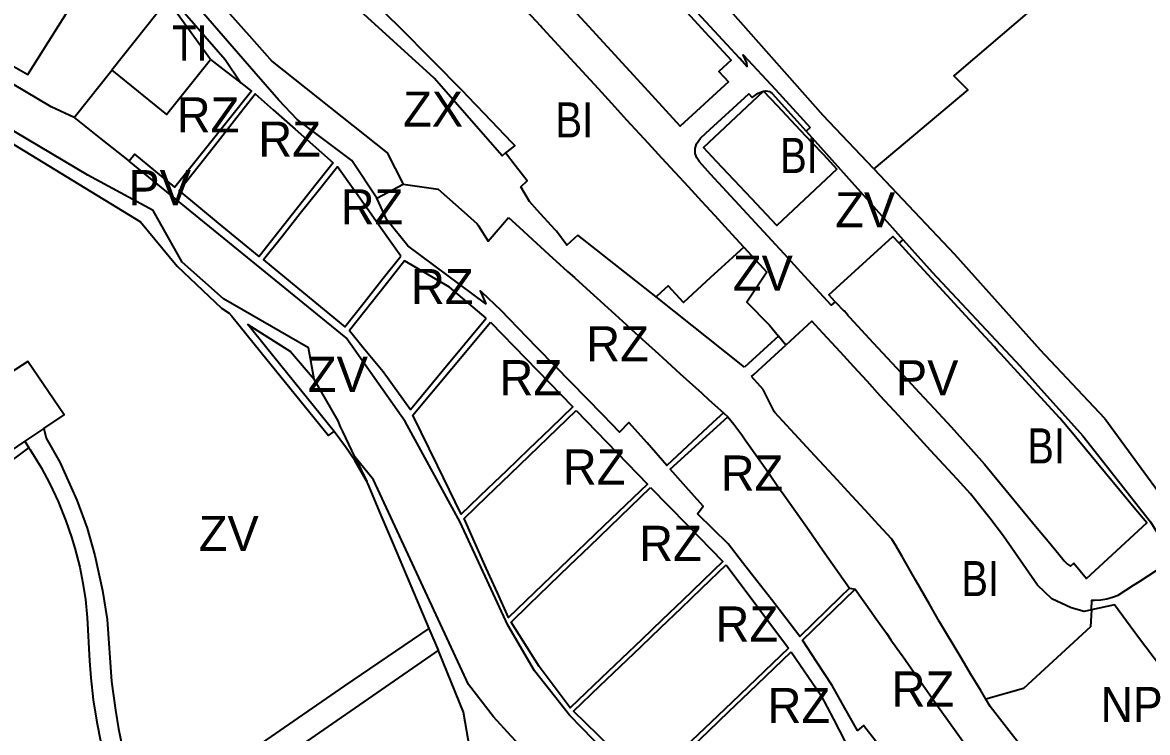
# Model space of a CAD drawing. Extents: x -650451 to -642268, y -1075216 to -1066610.
# Drawn here: x -646557.7 to -646077.2, y -1072296.6 to -1071993.3 of the extents above; entities that cross this region are included whole.
import ezdxf

# ---------------------------------------------------------------- set-up
doc = ezdxf.new("R2010")
doc.units = 0
doc.header["$LTSCALE"] = 6
doc.layers.add('1', color=7, linetype='Continuous', lineweight=35)
doc.layers.add('2', color=7, linetype='Continuous')
doc.layers.add('3', color=7, linetype='Continuous')

msp = doc.modelspace()

# ---------------------------------------------------------------- linework, layer by layer
at = {"layer": '1'}
for p, q in [((-646472.83, -1071985.44), (-646460.91, -1071998.89)), ((-646535.68, -1072033.89), (-646519.64, -1072013.69)), ((-646194.191, -1072055.797), (-646215.94, -1072032.8)), ((-646221.31, -1072038.09), (-646222.96, -1072039.72)), ((-646406.46, -1072068.39), (-646395.21, -1072062.3)), ((-646337.87, -1072073.42), (-646341.21, -1072069.74)), ((-646330.33, -1072081.74), (-646337.87, -1072073.42)), ((-646196.17, -1072069.75), (-646193.3, -1072072.98)), ((-646338.2, -1072087.54), (-646331.17, -1072093.93)), ((-646183.28, -1072087.62), (-646181.609, -1072086.079)), ((-646331.17, -1072093.93), (-646329.95, -1072095.03)), ((-646329.95, -1072095.03), (-646324.94, -1072099.59)), ((-646293.83, -1072105.24), (-646307.16, -1072094.67)), ((-646324.94, -1072099.59), (-646321.85, -1072102.39)), ((-646287.16, -1072110.52), (-646293.83, -1072105.24)), ((-646249.36, -1072140.5), (-646287.16, -1072110.52)), ((-646306.22, -1072116.58), (-646299.95, -1072122.27)), ((-646299.95, -1072122.27), (-646299.17, -1072122.98)), ((-646299.17, -1072122.98), (-646291.65, -1072129.81)), ((-646231.72, -1072131.08), (-646234.9, -1072127.22)), ((-646234.64, -1072133.77), (-646231.72, -1072131.08)), ((-646245.39, -1072143.64), (-646234.64, -1072133.77)), ((-646095.44, -1072162.47), (-646123.06, -1072133.18)), ((-646246.39, -1072144.56), (-646245.39, -1072143.64)), ((-646241.37, -1072150.02), (-646246.39, -1072144.56)), ((-646240.33, -1072152.1), (-646241.37, -1072150.02)), ((-646258.35, -1072160.04), (-646256.42, -1072161.7)), ((-646548.676, -1072166.737), (-646556.693, -1072172.159)), ((-646556.693, -1072172.159), (-646555.051, -1072174.933)), ((-646415.75, -1072178.82), (-646410.68, -1072189.36)), ((-646233.19, -1072194.16), (-646227.62, -1072202.1)), ((-646227.62, -1072202.1), (-646221.81, -1072210.37)), ((-646186.39, -1072214.03), (-646192.09, -1072207.86)), ((-646170.37, -1072241.84), (-646176.21, -1072231.64)), ((-646204.52, -1072235.01), (-646202.08, -1072235.38)), ((-646202.08, -1072235.38), (-646195.15, -1072245.18)), ((-646380.12, -1072261.44), (-646384.056, -1072252.138)), ((-646155.44, -1072267.16), (-646157.3, -1072264.05)), ((-646172.17, -1072277.7), (-646167.16, -1072284.79)), ((-646146.27, -1072282.34), (-646148.45, -1072278.73))]:
    msp.add_line(p, q, dxfattribs=at)
for points in [[(-646357.09, -1071925.59), (-646339.33, -1071906.58), (-646336.6, -1071910.5), (-646333.15, -1071915.44), (-646331.55, -1071917.74), (-646325.42, -1071925.87), (-646322.33, -1071930.79), (-646305.17, -1071949.86), (-646273.14, -1071985.13), (-646251.59, -1072008.34), (-646251.4, -1072008.54), (-646248.19, -1072012.02), (-646248.33, -1072010.57), (-646249.88, -1072007.03), (-646236.1, -1072021.93), (-646221.31, -1072038.09)], [(-646249.71, -1072089.21), (-646256.24, -1072082.11), (-646261.92, -1072075.92), (-646267.6, -1072069.74), (-646273.28, -1072063.55), (-646278.97, -1072057.37), (-646284.65, -1072051.18), (-646290.33, -1072045), (-646299.57, -1072034.94), (-646306.1, -1072027.84), (-646311.78, -1072021.65), (-646328.83, -1072003.1), (-646335.36, -1071995.99), (-646335.87, -1071995.44), (-646336.37, -1071994.89), (-646350.24, -1071979.79), (-646364.11, -1071964.7), (-646377.98, -1071949.6), (-646376.25, -1071948.01), (-646380.09, -1071943.87), (-646357.09, -1071925.59)], [(-646305.73, -1071933.35), (-646302.38, -1071937.06), (-646293.49, -1071946.89), (-646266.5, -1071975.69), (-646215.94, -1072032.8)], [(-646068.317, -1071937.555), (-646156.858, -1072013.393), (-646160, -1072016), (-646154, -1072022), (-646194.191, -1072055.797)], [(-646451.87, -1071956.88), (-646446.22, -1071959.67), (-646423.62, -1071970.84), (-646411.66, -1071980.54), (-646397.04, -1071994.94), (-646382.64, -1072009.55), (-646369.88, -1072022.49), (-646367.74, -1072024.72), (-646360.53, -1072032.22), (-646348.89, -1072044.34), (-646347.47, -1072045.83), (-646349.03, -1072047.09), (-646351.45, -1072049.03)], [(-646406.46, -1072068.39), (-646417.04, -1072052.27), (-646440.49, -1072034.75), (-646448.23, -1072026.42), (-646458.91, -1072014.27), (-646493.47, -1071974.228), (-646501.961, -1071969.983), (-646511.058, -1071967.447), (-646523.641, -1071965.612)], [(-646277.19, -1071985.4), (-646264.6, -1071999.11), (-646263.65, -1072000.13), (-646255.13, -1072009.41), (-646260.28, -1072014.15), (-646256.22, -1072018.57), (-646276.84, -1072037.51), (-646290.37, -1072022.79), (-646317.43, -1071993.33), (-646342.81, -1071965.72)], [(-646565.01, -1072016.41), (-646561.43, -1072012.01), (-646555.52, -1072015.55), (-646531.63, -1071977.65), (-646527.311, -1071971.141)], [(-646527.311, -1071971.141), (-646512.302, -1071973.329), (-646504.127, -1071975.607), (-646497.27, -1071979.036), (-646471.146, -1072009.088), (-646464.53, -1072019.09)], [(-646477.45, -1072009.12), (-646495.86, -1071983.75), (-646519.64, -1072013.69)], [(-646351.45, -1072049.03), (-646352.93, -1072050.22), (-646381.87, -1072017.05), (-646416.67, -1071985.38)], [(-646460.91, -1071998.89), (-646451.18, -1072009.98), (-646402.01, -1072048.91), (-646395.21, -1072062.3)], [(-646519.64, -1072013.69), (-646508.3, -1072022.8), (-646496.18, -1072032.53), (-646477.45, -1072009.12)], [(-646477.45, -1072009.12), (-646471.08, -1072014.04), (-646464.53, -1072019.09)], [(-646535.68, -1072033.89), (-646545.56, -1072029.37), (-646561.99, -1072019.42), (-646565.01, -1072016.41)], [(-646464.53, -1072019.09), (-646459.97, -1072022.61), (-646479.03, -1072046.49), (-646485.91, -1072055.1), (-646492.67, -1072063.57), (-646509.76, -1072049.5), (-646512.21, -1072052.57)], [(-646210.58, -1072112.56), (-646212.32, -1072114.01), (-646225.32, -1072099.94), (-646226.6, -1072098.55), (-646229.5, -1072095.41), (-646230.77, -1072094.02), (-646263.88, -1072058.07), (-646268.56, -1072052.8), (-646269.73, -1072051.09), (-646270.37, -1072049.18), (-646270.43, -1072047.11), (-646269.83, -1072045.14), (-646268.09, -1072042.67), (-646265.9, -1072040.56), (-646247.48, -1072023.7), (-646246.04, -1072025.34), (-646243.54, -1072023.53), (-646241.66, -1072022.73), (-646241.21, -1072022.61)], [(-646241.21, -1072022.61), (-646240.24, -1072022.48), (-646238.72, -1072022.79), (-646237.49, -1072023.64), (-646222.96, -1072039.72)], [(-646433.16, -1072145.61), (-646435.6, -1072132.24), (-646471.84, -1072111.32), (-646489.58, -1072095.65), (-646501.87, -1072073.55), (-646529.83, -1072058.46), (-646576.63, -1072030.7)], [(-646535.68, -1072033.89), (-646524.34, -1072042.92), (-646512.21, -1072052.57)], [(-646573.05, -1072038.46), (-646507.28, -1072078.4), (-646491.69, -1072097.45), (-646472.72, -1072115.38), (-646469.41, -1072117.44), (-646468.35, -1072118.76), (-646455.75, -1072134.29), (-646426.98, -1072169.74), (-646424.56, -1072167.96)], [(-646222.96, -1072039.72), (-646197.45, -1072068.32), (-646196.17, -1072069.75)], [(-646341.21, -1072069.74), (-646344.94, -1072063.53), (-646342.13, -1072060.94), (-646347.32, -1072054.31), (-646351.45, -1072049.03)], [(-646000.45, -1072615.28), (-645999.14, -1072611.29), (-646006.21, -1072593.04), (-646009.27, -1072582.89), (-646016.46, -1072568.07), (-646027.37, -1072549.05), (-646034.83, -1072536.97), (-646054.33, -1072506.16), (-646088.86, -1072457.93), (-646132.34, -1072412.37), (-646164.02, -1072390), (-646206.07, -1072366.43), (-646248.46, -1072343.52), (-646270.62, -1072332.33), (-646289.9, -1072320.26), (-646308.74, -1072304.97), (-646324.17, -1072289.15), (-646339.07, -1072270.33), (-646350.46, -1072250.81), (-646370.83, -1072206.8), (-646394.24, -1072163.81), (-646419.55, -1072128.03), (-646512.21, -1072052.57)], [(-646194.191, -1072055.797), (-646159.66, -1072092.31), (-646123.06, -1072133.18)], [(-646395.21, -1072062.3), (-646380.25, -1072064.44), (-646369.14, -1072074.36), (-646363.59, -1072079.32), (-646363.04, -1072080.16), (-646358.85, -1072086.64), (-646350.2, -1072076.65)], [(-646548.676, -1072166.737), (-646539.94, -1072160.83), (-646555.49, -1072138.17), (-646563.11, -1072143.03), (-646577.08, -1072118.7), (-646577.41, -1072117.76), (-646583.9, -1072106.42), (-646585.08, -1072104.81), (-646591.02, -1072094.4), (-646593.13, -1072091.01), (-646595.86, -1072086.82), (-646598.67, -1072081.55), (-646600.22, -1072077.86), (-646600.8, -1072075.94), (-646601.16, -1072074.07), (-646601.42, -1072071.01), (-646601, -1072067.55)], [(-646258.35, -1072160.04), (-646262.9, -1072164.17), (-646282.52, -1072182.54), (-646290.99, -1072172.91), (-646298.75, -1072164.1), (-646302.8, -1072168.3), (-646309.8, -1072161.1), (-646316.86, -1072153.83), (-646330.1, -1072140.22), (-646338.01, -1072132.07), (-646345.99, -1072123.86), (-646353.47, -1072116.17), (-646361.48, -1072108.67), (-646362.33, -1072107.88), (-646359.91, -1072113.46), (-646393.18, -1072088.66), (-646402.15, -1072077.6), (-646406.46, -1072068.39)], [(-646193.3, -1072072.98), (-646192, -1072074.43), (-646181.609, -1072086.079)], [(-646350.2, -1072076.65), (-646345.68, -1072080.75), (-646338.2, -1072087.54)], [(-646320.51, -1072084.13), (-646325.21, -1072088.45), (-646329.72, -1072082.41), (-646330.33, -1072081.74)], [(-646307.16, -1072094.67), (-646312.51, -1072090.43), (-646320.51, -1072084.13)], [(-646210.58, -1072112.56), (-646213.3, -1072109.63), (-646185.99, -1072084.68), (-646183.28, -1072087.62)], [(-646210.58, -1072112.56), (-646206.86, -1072116.57), (-646206.72, -1072116.45), (-646205.24, -1072118.2), (-646205.31, -1072118.26), (-646204.46, -1072119.17), (-646194.35, -1072130.11), (-646184.48, -1072140.8), (-646179.6, -1072146.08), (-646174.71, -1072151.38), (-646168.36, -1072158.25), (-646161.13, -1072166.08), (-646156.19, -1072171.44), (-646151.51, -1072176.71), (-646146.89, -1072182.04), (-646142.27, -1072187.57), (-646124.33, -1072209.25), (-646119.73, -1072214.8), (-646115.14, -1072220.36), (-646112.76, -1072223.22), (-646111.38, -1072224.63), (-646110.19, -1072225.59), (-646108.74, -1072224.25), (-646103.34, -1072230.77), (-646077.57, -1072207.09), (-646082.96, -1072200.57), (-646101.36, -1072178.37), (-646106.75, -1072171.85), (-646109.31, -1072168.77), (-646114.7, -1072162.25), (-646134.19, -1072141.04), (-646139.91, -1072134.82), (-646141.26, -1072133.34), (-646142.61, -1072131.87), (-646148.33, -1072125.65), (-646158.07, -1072115.05), (-646162.94, -1072109.74), (-646167.82, -1072104.44), (-646177.56, -1072093.84), (-646183.28, -1072087.62)], [(-646181.609, -1072086.079), (-646169.22, -1072099.97), (-646131.65, -1072140.05)], [(-646249.71, -1072089.21), (-646260.96, -1072099.56), (-646263.84, -1072102.2), (-646275.48, -1072112.89), (-646282.01, -1072105.79), (-646284.89, -1072108.44), (-646287.16, -1072110.52)], [(-646249.71, -1072089.21), (-646239.86, -1072099.92), (-646248.39, -1072112.76), (-646238.72, -1072122.6), (-646234.9, -1072127.22)], [(-646321.85, -1072102.39), (-646313.68, -1072109.81), (-646312.43, -1072110.94), (-646306.22, -1072116.58)], [(-646101.18, -1072244.23), (-646104.22, -1072244.89), (-646109.89, -1072243.31), (-646118.15, -1072239.49), (-646124.2, -1072233.64), (-646129.07, -1072226.71), (-646133.87, -1072219.72), (-646138.75, -1072212.79), (-646144.61, -1072205.07), (-646146.83, -1072202.19), (-646152.86, -1072194.62), (-646158.54, -1072188.44), (-646164.22, -1072182.25), (-646169.91, -1072176.07), (-646175.59, -1072169.88), (-646182.12, -1072162.78), (-646183.47, -1072161.3), (-646191.35, -1072152.72), (-646197.04, -1072146.54), (-646202.72, -1072140.35), (-646208.4, -1072134.17), (-646214.08, -1072127.98), (-646217.46, -1072124.31), (-646220.61, -1072120.88), (-646231.72, -1072131.08)], [(-646424.56, -1072167.96), (-646453.42, -1072132.4), (-646461.56, -1072122.36), (-646443.3, -1072133.79), (-646433.16, -1072145.61)], [(-646291.65, -1072129.81), (-646286.09, -1072134.85), (-646284.31, -1072136.47), (-646276.92, -1072143.18), (-646267.64, -1072151.6)], [(-646234.9, -1072127.22), (-646238.03, -1072130.1), (-646249.36, -1072140.5)], [(-646131.65, -1072140.05), (-646104.85, -1072169.81), (-646075.91, -1072206.65), (-646073.62, -1072210.24), (-646071.06, -1072214.28), (-646065.77, -1072222.6), (-646064.24, -1072225.01)], [(-646415.75, -1072178.82), (-646420.97, -1072167.95), (-646421.9, -1072166.01), (-646422.94, -1072163.48), (-646433.16, -1072145.61)], [(-646267.64, -1072151.6), (-646264.53, -1072154.43), (-646258.35, -1072160.04)], [(-646211.37, -1072186.94), (-646219.27, -1072178.37), (-646236.35, -1072159.85), (-646236.66, -1072159.51), (-646240.33, -1072152.1)], [(-646204.52, -1072235.01), (-646208.61, -1072238.99), (-646225.67, -1072255.58), (-646231.75, -1072247.73), (-646237.85, -1072239.85), (-646244.07, -1072231.82), (-646250.19, -1072223.93), (-646256.28, -1072216.06), (-646262.75, -1072209.7), (-646269.39, -1072203.17), (-646267.04, -1072199.93), (-646274.38, -1072191.62), (-646281.09, -1072184.04), (-646256.42, -1072161.7)], [(-646256.42, -1072161.7), (-646253.99, -1072164.89), (-646250.54, -1072169.43)], [(-646095.44, -1072162.47), (-646067.08, -1072201.18), (-646008.065, -1072293.22)], [(-646548.676, -1072166.737), (-646547.606, -1072170.835), (-646541.822, -1072181.102), (-646534.527, -1072197.411), (-646530.167, -1072209.31), (-646526.798, -1072221.011), (-646523.628, -1072235.883), (-646521.646, -1072248.378), (-646519.756, -1072274.861), (-646518.079, -1072287.051), (-646516.692, -1072294.983), (-646515.305, -1072301.925)], [(-646410.68, -1072189.36), (-646415.84, -1072180.43), (-646419.83, -1072174.51), (-646424.56, -1072167.96)], [(-646250.54, -1072169.43), (-646249.07, -1072171.52), (-646239.32, -1072185.42), (-646234.49, -1072192.31), (-646233.19, -1072194.16)], [(-646556.693, -1072172.159), (-646592.2, -1072196.17), (-646593.85, -1072195.48), (-646643.55, -1072233.5), (-646737.449, -1072305.019), (-646758.684, -1072283.41), (-646766.842, -1072275.063)], [(-646518.208, -1072321.92), (-646587.666, -1072389.082), (-646606.848, -1072405.785), (-646712.634, -1072292.59), (-646555.051, -1072174.933)], [(-646555.051, -1072174.933), (-646554.56, -1072175.629), (-646549.793, -1072183.38), (-646546.09, -1072190.428), (-646542.484, -1072197.985), (-646539.168, -1072206.122), (-646536.772, -1072213.218), (-646535.344, -1072217.844), (-646533.286, -1072226.031), (-646531.93, -1072232.861), (-646530.892, -1072239.747), (-646530.188, -1072247.442), (-646529.182, -1072265.941), (-646528.566, -1072273.308), (-646527.5, -1072282.657), (-646526, -1072292.201), (-646524.282, -1072300.849), (-646522.007, -1072309.932), (-646519.417, -1072318.408), (-646518.208, -1072321.92)], [(-645943.65, -1072789.47), (-645967.22, -1072787.26), (-645967.91, -1072767.31), (-645970.61, -1072747.97), (-645973.9, -1072738.22), (-645989.39, -1072712.38), (-646003.73, -1072680.75), (-646016.23, -1072641.16), (-646028.02, -1072609.24), (-646040.96, -1072577.06), (-646054.2, -1072554.48), (-646073.49, -1072523.45), (-646108.36, -1072475.46), (-646151.34, -1072429.6), (-646183.23, -1072407.45), (-646225.13, -1072384.18), (-646267.31, -1072361.39), (-646298.76, -1072344.13), (-646326.33, -1072322.56), (-646349.05, -1072298.16), (-646356.62, -1072289.89), (-646367.24, -1072276.07), (-646407.81, -1072188.6), (-646415.75, -1072178.82)], [(-646384.056, -1072252.138), (-646391.77, -1072233.91), (-646399.6, -1072215.39), (-646404.67, -1072203.42), (-646410.14, -1072190.49), (-646410.68, -1072189.36)], [(-646192.09, -1072207.86), (-646197.78, -1072201.68), (-646203.48, -1072195.51), (-646211.37, -1072186.94)], [(-646221.81, -1072210.37), (-646216.04, -1072218.6), (-646204.52, -1072235.01)], [(-646176.21, -1072231.64), (-646182.05, -1072221.45), (-646184.57, -1072217.04), (-646186.39, -1072214.03)], [(-646101.18, -1072244.23), (-646100.98, -1072240.01), (-646099.81, -1072240.09), (-646097.13, -1072239.87), (-646094.63, -1072239.5), (-646091.73, -1072238.71), (-646089.83, -1072237.95), (-646083.18, -1072233.66), (-646080.67, -1072232.05), (-646070.02, -1072225.18), (-646067.87, -1072224.34), (-646065.64, -1072224.26), (-646064.24, -1072225.01)], [(-646124.57, -1072345.05), (-646145.57, -1072363.62), (-646152.42, -1072355.16), (-646156.78, -1072349.77), (-646155.77, -1072349.02), (-646158.29, -1072345.96), (-646159.76, -1072344.16), (-646162.06, -1072343.4), (-646165.77, -1072339.12), (-646172.77, -1072331.06), (-646179.53, -1072323.27), (-646177.12, -1072321.19), (-646184.36, -1072311.83), (-646191.42, -1072302.72), (-646198.51, -1072293.55), (-646201.14, -1072295.81), (-646206.54, -1072286.21), (-646211.97, -1072276.57), (-646218.5, -1072266.6), (-646224.64, -1072257.23), (-646202.08, -1072235.38)], [(-646157.3, -1072264.05), (-646166.08, -1072249.31), (-646170.37, -1072241.84)], [(-646014.64, -1072358.74), (-646016.43, -1072355.88), (-646026.55, -1072339.67), (-646037.37, -1072322.92), (-646048.32, -1072305.81), (-646057.93, -1072287.58), (-646069.73, -1072270.99), (-646071.3, -1072268.92), (-646081.08, -1072256.01), (-646091.27, -1072242.07), (-646101.18, -1072244.23)], [(-646195.15, -1072245.18), (-646193.5, -1072247.52), (-646188.78, -1072254.2), (-646186.83, -1072256.95)], [(-646101.18, -1072244.23), (-646101.53, -1072251.45), (-646130.2, -1072277.79), (-646146.27, -1072282.34)], [(-646455.557, -1072301.131), (-646420.085, -1072276.737), (-646384.056, -1072252.138)], [(-646380.12, -1072261.44), (-646459.03, -1072316.137), (-646465.227, -1072321.127), (-646473.069, -1072327.765), (-646485.656, -1072338.908), (-646504.244, -1072357.026)], [(-646366.62, -1072303.53), (-646369.35, -1072287.95), (-646379.86, -1072262.05), (-646380.12, -1072261.44)], [(-646186.83, -1072256.95), (-646182.5, -1072263.09), (-646181.94, -1072263.89), (-646177.05, -1072270.8), (-646175.95, -1072272.36), (-646172.17, -1072277.7)], [(-646148.45, -1072278.73), (-646152.81, -1072271.52), (-646155.44, -1072267.16)], [(-646167.16, -1072284.79), (-646160.44, -1072294.29), (-646156.16, -1072300.36), (-646149.48, -1072309.81)], [(-646129.15, -1072305.06), (-646135.43, -1072296.99), (-646144.38, -1072285.47), (-646146.27, -1072282.34)]]:
    msp.add_lwpolyline(points, dxfattribs=at)
for points in [[(-646425.08, -1072053.19), (-646432.34, -1072062.4), (-646440.22, -1072072.4), (-646448.29, -1072082.63), (-646456.63, -1072093.22), (-646473.97, -1072078.95), (-646490.82, -1072065.09), (-646482.08, -1072054.04), (-646474.16, -1072044.02), (-646466.2, -1072033.79), (-646458.43, -1072023.79), (-646450.68, -1072030.62), (-646441.35, -1072038.85)], [(-646241.21, -1072022.61), (-646235.42, -1072028.76), (-646225.56, -1072039.24), (-646220.62, -1072044.48), (-646215.69, -1072049.73), (-646209.9, -1072055.89), (-646235.54, -1072080.01), (-646246.37, -1072068.5), (-646251.27, -1072063.3), (-646261.27, -1072052.66), (-646266.87, -1072046.71)], [(-646396.16, -1072093.12), (-646404.5, -1072081.26), (-646409.87, -1072073.68), (-646423.17, -1072054.9), (-646431.45, -1072065.31), (-646439.1, -1072074.94), (-646446.74, -1072084.55), (-646454.82, -1072094.71), (-646437.75, -1072108.75), (-646420.06, -1072123.31), (-646411.77, -1072112.84), (-646404.2, -1072103.27)], [(-646359.74, -1072119.55), (-646375.35, -1072106.35), (-646394.62, -1072095.11), (-646402.31, -1072104.86), (-646418.13, -1072124.9), (-646412.18, -1072132.12), (-646403.75, -1072142.38), (-646392.06, -1072158.59), (-646377.99, -1072141.59)], [(-646357.8, -1072121.32), (-646322.64, -1072157.49), (-646332.25, -1072166.72), (-646341.68, -1072175.77), (-646351.05, -1072184.77), (-646359.02, -1072192.42), (-646370.34, -1072203.29), (-646380.5, -1072182.54), (-646391.02, -1072161.06), (-646374.38, -1072141.15)], [(-646321.23, -1072159.05), (-646290.82, -1072190.5), (-646300.14, -1072199.47), (-646309.52, -1072208.48), (-646328.19, -1072226.43), (-646350.13, -1072247.52), (-646354.89, -1072236.93), (-646359.65, -1072226.35), (-646369.17, -1072205.2), (-646359.42, -1072195.82), (-646349.33, -1072186.1)], [(-646289.45, -1072191.87), (-646274.04, -1072207.69), (-646258.57, -1072223.58), (-646267.19, -1072231.84), (-646275.87, -1072240.15), (-646284.57, -1072248.5), (-646293.28, -1072256.84), (-646310.6, -1072273.44), (-646323.76, -1072286.05), (-646337.06, -1072268.4), (-646349.03, -1072249.42), (-646341.28, -1072241.94), (-646324.05, -1072225.29), (-646315.47, -1072217.01), (-646306.75, -1072208.58), (-646298.12, -1072200.24)], [(-646257.17, -1072225.02), (-646243.64, -1072243.12), (-646230.6, -1072260.59), (-646237.45, -1072267.15), (-646254.8, -1072283.76), (-646263.55, -1072292.13), (-646271.98, -1072300.2), (-646280.78, -1072308.62), (-646289.72, -1072317.17), (-646306.56, -1072302.91), (-646322.37, -1072287.43), (-646311.21, -1072276.74), (-646302.49, -1072268.4), (-646293.54, -1072259.83), (-646285.1, -1072251.76), (-646276.46, -1072243.48), (-646267.59, -1072235)], [(-646229.47, -1072262.11), (-646216.82, -1072280.7), (-646211.41, -1072290.93), (-646206.31, -1072300.61), (-646225.91, -1072319.47), (-646234.63, -1072327.85), (-646248.36, -1072341.06), (-646268.81, -1072330.59), (-646278.46, -1072324.39), (-646287.88, -1072318.32), (-646264.64, -1072295.96), (-646256.03, -1072287.68), (-646247.38, -1072279.35)]]:
    msp.add_lwpolyline(points, close=True, dxfattribs=at)

# ---------------------------------------------------------------- texts
at = {"layer": '2'}
for s, width, p in [('TI', 0.85, (-646493.87, -1072009.54)), ('BI', 0.85, (-646330.094, -1072042.393)), ('BI', 0.85, (-646234.151, -1072057.581)), ('BI', 0.85, (-646128.577, -1072181.678)), ('BI', 0.85, (-646156.73, -1072238.355)), ('NP', 0.95, (-646097.244, -1072292.132))]:
    msp.add_text(s, height=15, dxfattribs=dict(at, width=width)).set_placement(p)
for s, p in [('RZ', (-646491.872, -1072040.23)), ('ZX', (-646395.193, -1072037.765)), ('RZ', (-646457.042, -1072050.605)), ('PV', (-646512.536, -1072071.337)), ('RZ', (-646421.842, -1072079.506)), ('ZV', (-646210.61, -1072080.808)), ('ZV', (-646254.321, -1072107.85)), ('RZ', (-646391.829, -1072113.595)), ('RZ', (-646316.981, -1072138.05)), ('ZV', (-646435.83, -1072151.11)), ('RZ', (-646354.034, -1072152.501)), ('PV', (-646184.734, -1072152.541)), ('RZ', (-646326.986, -1072190.666)), ('RZ', (-646259.549, -1072193.259)), ('RZ', (-646294.379, -1072223.272)), ('RZ', (-646261.772, -1072257.732)), ('RZ', (-646186.555, -1072285.521)), ('RZ', (-646239.541, -1072292.562))]:
    msp.add_text(s, height=15, dxfattribs=at).set_placement(p)
at = {"layer": '3'}
msp.add_text('ZV', height=15, dxfattribs=at).set_placement((-646482.453, -1072219.067))

doc.saveas('drawing.dxf')
